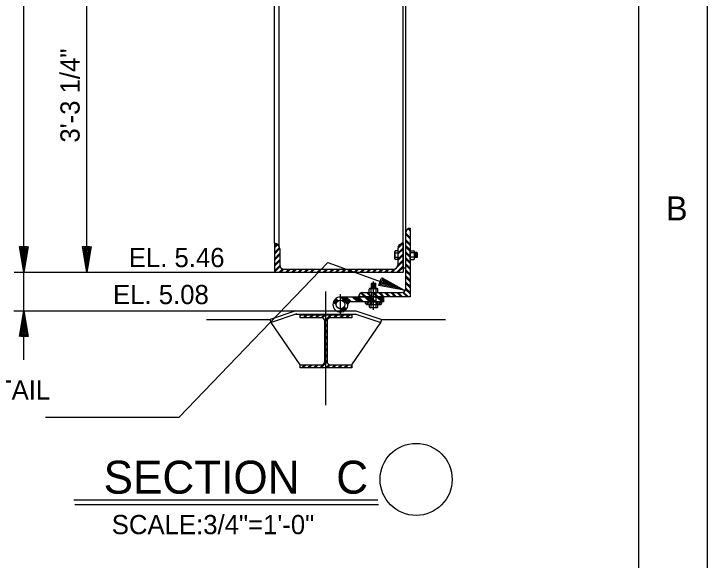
# Model space of a CAD drawing. Extents: x 0.6 to 54, y 0.6 to 38.
# Drawn here: x 47.23 to 53.96, y 11.41 to 16.72 of the extents above; entities that cross this region are included whole.
import ezdxf

# ---------------------------------------------------------------- set-up
doc = ezdxf.new("R2010")
doc.units = 0
for name, color, linetype in [('Level 1', 7, 'Continuous'), ('Level 10', 7, 'Continuous'), ('Level 13', 7, 'Continuous'), ('Level 2', 7, 'Continuous'), ('Level 25', 7, 'Continuous'), ('Level 3', 7, 'Continuous'), ('Level 36', 7, 'Continuous'), ('Level 50', 7, 'Continuous')]:
    doc.layers.add(name, color=color, linetype=linetype)

msp = doc.modelspace()

# ---------------------------------------------------------------- linework, layer by layer
at = {"layer": 'Level 1'}
msp.add_line((50.6601, 13.8913), (50.7804, 13.8913), dxfattribs=at)
for points in [[(0.625, 37.9583), (53.9583, 37.9583), (53.9583, 0.625), (0.625, 0.625)], [(2.625, 37.2917), (53.2917, 37.2917), (53.2917, 1.2917), (2.625, 1.2917)]]:
    msp.add_lwpolyline(points, close=True, dxfattribs=at)
for centre, start, end in [((50.6625, 13.9174), 180, 270), ((50.7771, 13.9174), 270, 0)]:
    msp.add_arc(centre, 0.026, start, end, dxfattribs=at)
at = {"layer": 'Level 10'}
for p, q in [((50.6431, 13.9174), (50.6372, 13.9115)), ((50.649, 13.9174), (50.6386, 13.907)), ((50.6725, 13.9174), (50.6498, 13.8947)), ((50.6784, 13.9174), (50.6539, 13.8928)), ((50.6956, 13.9109), (50.6759, 13.8913)), ((50.6956, 13.9051), (50.6818, 13.8913)), ((50.7684, 13.9174), (50.7441, 13.8931)), ((50.7625, 13.9174), (50.7441, 13.899)), ((50.7919, 13.9174), (50.7659, 13.8913)), ((50.7978, 13.9174), (50.7718, 13.8913))]:
    msp.add_line(p, q, dxfattribs=at)
at = {"layer": 'Level 13'}
for p, q in [((50.9252, 14.4087), (50.9284, 14.4143)), ((50.9252, 14.3362), (50.9252, 14.4087)), ((50.9591, 14.4143), (50.9284, 14.4143)), ((50.9591, 14.3306), (50.9591, 14.4143)), ((51.0743, 14.3306), (51.0743, 14.4143)), ((51.0743, 14.4143), (51.1141, 14.4143)), ((51.1173, 14.4087), (51.1141, 14.4143)), ((51.1173, 14.3362), (51.1173, 14.4087)), ((50.9283, 14.3934), (50.9591, 14.3934)), ((50.9283, 14.3515), (50.9591, 14.3515)), ((50.9606, 14.3967), (50.9591, 14.3967)), ((50.9591, 14.3518), (50.9591, 14.3306)), ((50.9606, 14.3482), (50.9591, 14.3482)), ((51.0728, 14.3967), (51.0743, 14.3967)), ((51.0728, 14.3482), (51.0743, 14.3482)), ((51.1142, 14.3934), (51.0743, 14.3934)), ((51.1142, 14.3515), (51.0743, 14.3515)), ((51.1408, 14.3967), (51.1173, 14.3967)), ((51.1408, 14.3482), (51.1173, 14.3482)), ((51.1226, 14.3544), (51.1226, 14.3904)), ((51.1286, 14.3482), (51.1286, 14.3967)), ((51.1347, 14.3544), (51.1347, 14.3904)), ((51.1408, 14.3482), (51.1408, 14.3967)), ((51.1408, 14.3967), (51.1468, 14.3907)), ((51.1408, 14.3482), (51.1468, 14.3543)), ((51.1468, 14.3543), (51.1468, 14.3907)), ((50.9252, 14.3362), (50.9284, 14.3306)), ((50.9591, 14.3306), (50.9284, 14.3306)), ((51.0743, 14.3306), (51.1141, 14.3306)), ((51.1173, 14.3362), (51.1141, 14.3306)), ((50.6993, 14.0974), (50.7015, 14.0996)), ((50.6993, 14.0975), (50.741, 14.0975)), ((50.6993, 14.0495), (50.6993, 14.0974)), ((50.6993, 14.0891), (50.741, 14.0891)), ((50.6993, 14.0809), (50.741, 14.0809)), ((50.6993, 14.0725), (50.741, 14.0725)), ((50.7015, 14.0996), (50.7389, 14.0996)), ((50.7098, 14.0934), (50.7316, 14.0934)), ((50.7098, 14.085), (50.7316, 14.085)), ((50.7098, 14.0766), (50.7316, 14.0766)), ((50.7098, 14.0684), (50.7316, 14.0684)), ((50.741, 14.0973), (50.7389, 14.0996)), ((50.741, 14.0495), (50.741, 14.0973)), ((50.6785, 14.0079), (50.6785, 14.0412)), ((50.687, 14.0495), (50.7534, 14.0495)), ((50.6957, 14.0079), (50.6957, 14.0412)), ((50.6993, 14.0641), (50.741, 14.0641)), ((50.6993, 14.0559), (50.741, 14.0559)), ((50.6993, 14.0079), (50.6993, 13.8906)), ((50.7098, 14.06), (50.7316, 14.06)), ((50.7098, 14.0516), (50.7316, 14.0516)), ((50.741, 14.0079), (50.741, 13.8906)), ((50.745, 14.0079), (50.745, 14.0412)), ((50.7618, 14.0079), (50.7618, 14.0412)), ((50.3383, 13.934), (50.361, 13.9113)), ((50.3398, 13.9362), (50.3623, 13.9137)), ((50.3414, 13.9383), (50.3634, 13.9162)), ((50.3431, 13.9403), (50.3653, 13.9181)), ((50.3448, 13.9422), (50.3669, 13.9201)), ((50.3466, 13.9441), (50.3687, 13.922)), ((50.3486, 13.9458), (50.3706, 13.9238)), ((50.3505, 13.9476), (50.3727, 13.9254)), ((50.3525, 13.9493), (50.3748, 13.927)), ((50.3545, 13.9509), (50.377, 13.9284)), ((50.8149, 13.9654), (50.3982, 13.9654)), ((50.3989, 13.9654), (50.4711, 13.8932)), ((50.4026, 13.9654), (50.4714, 13.8966)), ((50.4063, 13.9654), (50.4721, 13.8996)), ((50.4099, 13.9654), (50.4731, 13.9023)), ((50.4136, 13.9654), (50.4742, 13.9049)), ((50.4173, 13.9654), (50.4754, 13.9074)), ((50.421, 13.9654), (50.4772, 13.9093)), ((50.4247, 13.9654), (50.4791, 13.911)), ((50.4284, 13.9654), (50.4809, 13.9129)), ((50.4321, 13.9654), (50.4831, 13.9144)), ((50.4358, 13.9654), (50.4854, 13.9158)), ((50.4394, 13.9654), (50.488, 13.9169)), ((50.4431, 13.9654), (50.4908, 13.9178)), ((50.4468, 13.9654), (50.4939, 13.9184)), ((50.4505, 13.9654), (50.4974, 13.9186)), ((50.4541, 13.9654), (50.501, 13.9186)), ((50.4578, 13.9654), (50.5047, 13.9186)), ((50.5168, 13.9654), (50.5636, 13.9186)), ((50.5204, 13.9654), (50.5673, 13.9186)), ((50.5241, 13.9654), (50.571, 13.9186)), ((50.5278, 13.9654), (50.5747, 13.9186)), ((50.5315, 13.9654), (50.5784, 13.9186)), ((50.5315, 13.9654), (50.5747, 13.9223)), ((50.5352, 13.9654), (50.5821, 13.9186)), ((50.5389, 13.9654), (50.5857, 13.9186)), ((50.5426, 13.9654), (50.5894, 13.9186)), ((50.5462, 13.9654), (50.5931, 13.9186)), ((50.5499, 13.9654), (50.5968, 13.9186)), ((50.5536, 13.9654), (50.6005, 13.9186)), ((50.5573, 13.9654), (50.6042, 13.9186)), ((50.5609, 13.9654), (50.6078, 13.9186)), ((50.5646, 13.9654), (50.6115, 13.9186)), ((50.5683, 13.9654), (50.6152, 13.9186)), ((50.572, 13.9654), (50.6189, 13.9186)), ((50.5757, 13.9654), (50.6226, 13.9186)), ((50.6346, 13.9654), (50.6815, 13.9186)), ((50.6383, 13.9654), (50.6852, 13.9186)), ((50.642, 13.9654), (50.6889, 13.9186)), ((50.6457, 13.9654), (50.6926, 13.9186)), ((50.6493, 13.9654), (50.6962, 13.9186)), ((50.653, 13.9654), (50.6999, 13.9186)), ((50.6567, 13.9654), (50.7036, 13.9186)), ((50.6604, 13.9654), (50.7073, 13.9186)), ((50.6641, 13.9654), (50.7109, 13.9186)), ((50.6678, 13.9654), (50.7146, 13.9186)), ((50.6714, 13.9654), (50.7183, 13.9186)), ((50.6751, 13.9654), (50.722, 13.9186)), ((50.6788, 13.9654), (50.7257, 13.9186)), ((50.6825, 13.9654), (50.7294, 13.9186)), ((50.6862, 13.9654), (50.7331, 13.9186)), ((50.6899, 13.9654), (50.7367, 13.9186)), ((50.6935, 13.9654), (50.7404, 13.9186)), ((50.7524, 13.9654), (50.7993, 13.9186)), ((50.7561, 13.9654), (50.803, 13.9186)), ((50.7598, 13.9654), (50.8067, 13.9186)), ((50.7635, 13.9654), (50.8104, 13.9186)), ((50.7672, 13.9654), (50.8141, 13.9186)), ((50.7709, 13.9654), (50.8149, 13.9214)), ((50.7746, 13.9654), (50.8149, 13.9251)), ((50.7782, 13.9654), (50.8149, 13.9288)), ((50.7819, 13.9654), (50.8149, 13.9325)), ((50.7856, 13.9654), (50.8149, 13.9361)), ((50.7893, 13.9654), (50.8149, 13.9398)), ((50.7929, 13.9654), (50.8149, 13.9435)), ((50.7966, 13.9654), (50.8149, 13.9472)), ((50.8003, 13.9654), (50.8149, 13.9509)), ((50.804, 13.9654), (50.8149, 13.9546)), ((50.8077, 13.9654), (50.8149, 13.9583)), ((50.8114, 13.9654), (50.8149, 13.9619)), ((50.8149, 13.9654), (50.8149, 13.9186)), ((50.3295, 13.917), (50.3566, 13.8899)), ((50.3305, 13.9197), (50.3566, 13.8937)), ((50.3316, 13.9223), (50.3568, 13.8971)), ((50.3328, 13.9248), (50.3573, 13.9003)), ((50.3341, 13.9272), (50.358, 13.9033)), ((50.3354, 13.9295), (50.3588, 13.9061)), ((50.3368, 13.9318), (50.3598, 13.9088)), ((50.4311, 13.867), (50.4533, 13.8448)), ((50.4327, 13.8691), (50.4548, 13.847)), ((50.4341, 13.8713), (50.4566, 13.8488)), ((50.8149, 13.9186), (50.4972, 13.9186)), ((50.6791, 13.8913), (50.7624, 13.8913)), ((50.6791, 13.8678), (50.6791, 13.8913)), ((50.6963, 13.8676), (50.6963, 13.8913)), ((50.7456, 13.8677), (50.7456, 13.8913)), ((50.7624, 13.8678), (50.7624, 13.8913)), ((50.3956, 13.8509), (50.4227, 13.8238)), ((50.3993, 13.8509), (50.4254, 13.8248)), ((50.4028, 13.8511), (50.4279, 13.8259)), ((50.406, 13.8516), (50.4304, 13.8271)), ((50.409, 13.8523), (50.4329, 13.8284)), ((50.4118, 13.8531), (50.4352, 13.8297)), ((50.4145, 13.8542), (50.4375, 13.8311)), ((50.417, 13.8553), (50.4397, 13.8326)), ((50.4194, 13.8566), (50.4419, 13.8341)), ((50.4216, 13.8581), (50.4439, 13.8357)), ((50.4238, 13.8596), (50.4459, 13.8374)), ((50.4258, 13.8612), (50.4479, 13.8391)), ((50.4277, 13.8631), (50.4498, 13.8409)), ((50.4294, 13.8649), (50.4515, 13.8429)), ((50.6876, 13.8622), (50.7541, 13.8622))]:
    msp.add_line(p, q, dxfattribs=at)
msp.add_circle((50.3982, 13.8925), 0.0417, dxfattribs=at)
for centre, radius, start, end in [((50.9433, 14.4037), 0.0182, 149.71241, 214.51098), ((51.0992, 14.4038), 0.0182, 325.48902, 30.28759), ((50.9433, 14.3412), 0.0182, 145.48902, 210.28759), ((50.9979, 14.3722), 0.0727, 163.01837, 196.49659), ((51.0446, 14.3722), 0.0727, 343.50341, 16.98163), ((51.0992, 14.3412), 0.0182, 329.71241, 34.51098), ((50.6869, 14.041), 0.00844, 0.56585, 179.43412), ((50.7203, 14.009), 0.0406, 52.43432, 127.56565), ((50.7534, 14.0411), 0.00843, 0.4975, 179.50247), ((50.3982, 13.8925), 0.0729, 90, 0), ((50.4972, 13.8925), 0.026, 90, 180), ((50.6877, 13.8715), 0.00938, 203.16754, 335.99909), ((50.7208, 13.9191), 0.0569, 244.55188, 295.884), ((50.754, 13.8714), 0.00912, 202.37505, 337.19948)]:
    msp.add_arc(centre, radius, start, end, dxfattribs=at)
at = {"layer": 'Level 2'}
for p, q in [((50.6365, 13.9174), (50.8031, 13.9174)), ((50.6956, 13.8913), (50.6956, 13.9174)), ((50.7441, 13.8913), (50.7441, 13.9174))]:
    msp.add_line(p, q, dxfattribs=at)
at = {"layer": 'Level 25'}
for p, q in [((47.3239, 14.206), (47.3239, 20.7475)), ((49.7566, 14.4873), (49.7566, 19.2996)), ((49.8035, 14.4579), (49.8035, 19.2996)), ((51.0066, 14.2477), (51.0066, 19.2475)), ((51.0327, 14.2477), (51.0327, 19.2475)), ((47.9368, 14.206), (47.9368, 17.4766)), ((51.0743, 14.6086), (51.0548, 14.6281)), ((51.0743, 14.6246), (51.0667, 14.6322)), ((51.0743, 14.5441), (51.0327, 14.5857)), ((51.0743, 14.5304), (51.0327, 14.572)), ((49.7566, 14.4873), (49.7566, 14.206)), ((49.7815, 14.4809), (49.7566, 14.456)), ((49.7898, 14.4753), (49.7566, 14.4421)), ((51.0066, 14.5031), (50.957, 14.4535)), ((51.0066, 14.4892), (50.9571, 14.4396)), ((51.0066, 14.4873), (51.0066, 14.206)), ((51.0743, 14.4797), (51.0327, 14.5214)), ((51.0743, 14.4649), (51.0327, 14.5065)), ((49.8072, 14.4476), (49.7566, 14.3971)), ((49.8087, 14.4353), (49.7566, 14.3832)), ((49.8087, 14.4352), (49.8087, 14.2789)), ((50.9545, 14.4352), (50.9545, 14.2789)), ((51.0066, 14.4441), (50.9546, 14.3921)), ((51.0066, 14.4303), (50.9569, 14.3805)), ((51.0743, 14.4229), (51.0327, 14.4646)), ((51.0743, 14.409), (51.0327, 14.4507)), ((51.0743, 14.364), (51.0327, 14.4057)), ((49.8087, 14.3902), (49.7566, 14.3381)), ((49.8087, 14.3763), (49.7566, 14.3242)), ((51.0066, 14.3713), (50.9547, 14.3194)), ((51.0066, 14.3852), (50.955, 14.3336)), ((51.0743, 14.3501), (51.0327, 14.3918)), ((51.0743, 14.3051), (51.0327, 14.3467)), ((48.8338, 12.7979), (50.2758, 14.3016)), ((49.8087, 14.3304), (49.7566, 14.2783)), ((49.8087, 14.3165), (49.7566, 14.2645)), ((49.8087, 14.2715), (49.7566, 14.2194)), ((50.2758, 14.3016), (51.0179, 14.0309)), ((51.0066, 14.3124), (50.9002, 14.206)), ((51.0066, 14.3263), (50.9562, 14.2759)), ((51.0743, 14.2912), (51.0327, 14.3329)), ((51.0743, 14.2461), (51.0327, 14.2878)), ((51.0743, 14.2323), (51.0327, 14.2739)), ((47.2317, 14.206), (49.8992, 14.206)), ((47.3239, 13.8308), (47.3239, 14.206)), ((49.8126, 14.2614), (49.76, 14.2089)), ((49.8357, 14.2395), (49.8051, 14.2089)), ((49.8498, 14.2369), (49.8189, 14.206)), ((49.8984, 14.2355), (49.8683, 14.2054)), ((49.9142, 14.2375), (49.8822, 14.2054)), ((49.9569, 14.2351), (49.9272, 14.2054)), ((49.9716, 14.2359), (49.9411, 14.2054)), ((50.0168, 14.2361), (49.9862, 14.2054)), ((50.0309, 14.2363), (50.0001, 14.2054)), ((50.076, 14.2355), (50.046, 14.2054)), ((50.0919, 14.2375), (50.0598, 14.2054)), ((50.1345, 14.2379), (50.1049, 14.2083)), ((50.1493, 14.2388), (50.1188, 14.2083)), ((50.2031, 14.2366), (50.1731, 14.2066)), ((50.2189, 14.2386), (50.1869, 14.2066)), ((50.2616, 14.2362), (50.232, 14.2066)), ((50.2763, 14.237), (50.2459, 14.2066)), ((50.3216, 14.2372), (50.291, 14.2066)), ((50.3357, 14.2374), (50.3048, 14.2066)), ((50.3808, 14.2366), (50.3508, 14.2066)), ((50.3966, 14.2386), (50.3646, 14.2066)), ((50.4393, 14.2362), (50.4097, 14.2066)), ((50.454, 14.237), (50.4236, 14.2066)), ((50.4992, 14.2372), (50.4686, 14.2066)), ((50.5134, 14.2374), (50.4825, 14.2066)), ((50.5619, 14.2361), (50.5319, 14.206)), ((50.5778, 14.238), (50.5457, 14.206)), ((50.6204, 14.2356), (50.5908, 14.206)), ((50.6351, 14.2364), (50.6047, 14.206)), ((50.6804, 14.2366), (50.6498, 14.206)), ((50.6945, 14.2369), (50.6636, 14.206)), ((50.7396, 14.2361), (50.7096, 14.206)), ((50.7554, 14.238), (50.7234, 14.206)), ((50.7981, 14.2356), (50.7685, 14.206)), ((50.8128, 14.2364), (50.7824, 14.206)), ((50.8581, 14.2366), (50.8274, 14.206)), ((50.8722, 14.2369), (50.8413, 14.206)), ((50.9171, 14.2368), (50.8863, 14.206)), ((51.0066, 14.2674), (50.9453, 14.206)), ((51.0066, 14.2535), (50.9592, 14.206)), ((51.0066, 14.2084), (51.0042, 14.206)), ((51.0066, 14.2477), (51.0327, 14.2477)), ((51.0743, 14.1872), (51.0327, 14.2289)), ((51.0743, 14.1733), (51.0327, 14.215)), ((51.0743, 14.1283), (51.0327, 14.17)), ((51.0743, 14.1144), (51.0327, 14.1561)), ((50.7202, 13.8401), (50.7202, 14.1157)), ((51.0743, 14.0694), (51.0327, 14.111)), ((51.0743, 14.0555), (51.0327, 14.0971)), ((50.257, 12.9166), (50.257, 14.0188)), ((50.6333, 13.9662), (50.5966, 14.0028)), ((50.6471, 13.9662), (50.6068, 14.0066)), ((50.6922, 13.9662), (50.6505, 14.0079)), ((50.7061, 13.9662), (50.6644, 14.0079)), ((50.7511, 13.9662), (50.7094, 14.0079)), ((50.765, 13.9662), (50.7233, 14.0079)), ((50.81, 13.9662), (50.7684, 14.0079)), ((50.8239, 13.9662), (50.7823, 14.0079)), ((50.8689, 13.9662), (50.8273, 14.0079)), ((50.8828, 13.9662), (50.8412, 14.0079)), ((50.9279, 13.9662), (50.8862, 14.0079)), ((50.9418, 13.9662), (50.9001, 14.0079)), ((50.9868, 13.9662), (50.9451, 14.0079)), ((51.0007, 13.9662), (50.959, 14.0079)), ((51.0457, 13.9662), (51.0024, 14.0095)), ((51.0596, 13.9662), (51.012, 14.0138)), ((51.0743, 13.9966), (51.0311, 14.0398)), ((51.0743, 14.0104), (51.0327, 14.0521)), ((50.3972, 13.7906), (50.3972, 13.9926)), ((50.5882, 13.9662), (50.5762, 13.9783)), ((47.2277, 13.8308), (49.9654, 13.8308)), ((47.3239, 13.3551), (47.3239, 13.8308)), ((49.9654, 13.8308), (49.7154, 13.7475)), ((49.9752, 13.8012), (49.7252, 13.7178)), ((49.9654, 13.8308), (50.5487, 13.8308)), ((49.9654, 13.7996), (50.5487, 13.7996)), ((50.5388, 13.8012), (50.7888, 13.7178)), ((50.5487, 13.8308), (50.7987, 13.7475)), ((49.0965, 13.7475), (49.7154, 13.7475)), ((49.7253, 13.7178), (49.7154, 13.7475)), ((50.0065, 13.7939), (50.0065, 13.7939)), ((50.0065, 13.78), (50.0204, 13.7939)), ((50.035, 13.7635), (50.0654, 13.7939)), ((50.0489, 13.7635), (50.0793, 13.7939)), ((50.094, 13.7635), (50.1244, 13.7939)), ((50.1078, 13.7635), (50.1383, 13.7939)), ((50.1529, 13.7635), (50.1833, 13.7939)), ((50.1668, 13.7635), (50.1972, 13.7939)), ((50.2118, 13.7635), (50.2422, 13.7939)), ((50.2241, 13.7619), (50.2561, 13.7939)), ((50.2454, 13.7382), (50.3011, 13.7939)), ((50.2465, 13.7254), (50.315, 13.7939)), ((50.3297, 13.7635), (50.3601, 13.7939)), ((50.3435, 13.7635), (50.374, 13.7939)), ((50.3886, 13.7635), (50.419, 13.7939)), ((50.4025, 13.7635), (50.4329, 13.7939)), ((50.4475, 13.7635), (50.4779, 13.7939)), ((50.4614, 13.7635), (50.4918, 13.7939)), ((50.5064, 13.7635), (50.5082, 13.7653)), ((50.7888, 13.7178), (50.7987, 13.7475)), ((50.7987, 13.7475), (51.4182, 13.7475)), ((50.0065, 13.3077), (49.7252, 13.7178)), ((50.2465, 13.6804), (50.2682, 13.702)), ((50.2465, 13.6665), (50.2682, 13.6882)), ((50.5082, 13.3077), (50.7888, 13.7178)), ((50.2465, 13.6214), (50.2682, 13.6431)), ((50.2465, 13.6076), (50.2682, 13.6292)), ((50.2465, 13.5625), (50.2682, 13.5842)), ((50.2465, 13.5486), (50.2682, 13.5703)), ((50.2465, 13.5036), (50.2682, 13.5253)), ((50.2465, 13.4897), (50.2682, 13.5114)), ((50.2465, 13.4447), (50.2682, 13.4663)), ((50.2465, 13.4308), (50.2682, 13.4524)), ((50.2465, 13.3858), (50.2682, 13.4074)), ((50.197, 13.2773), (50.2682, 13.3485)), ((50.2109, 13.2773), (50.2689, 13.3353)), ((50.2465, 13.3719), (50.2682, 13.3935)), ((50.0202, 13.2773), (50.0506, 13.3077)), ((50.0341, 13.2773), (50.0645, 13.3077)), ((50.0791, 13.2773), (50.1095, 13.3077)), ((50.093, 13.2773), (50.1234, 13.3077)), ((50.138, 13.2773), (50.1684, 13.3077)), ((50.1519, 13.2773), (50.1823, 13.3077)), ((50.2559, 13.2773), (50.2888, 13.3102)), ((50.2698, 13.2773), (50.3002, 13.3077)), ((50.3148, 13.2773), (50.3452, 13.3077)), ((50.3287, 13.2773), (50.3591, 13.3077)), ((50.3737, 13.2773), (50.4042, 13.3077)), ((50.3876, 13.2773), (50.418, 13.3077)), ((50.4327, 13.2773), (50.4631, 13.3077)), ((50.4466, 13.2773), (50.477, 13.3077)), ((50.4916, 13.2773), (50.5082, 13.2939)), ((50.5055, 13.2773), (50.5082, 13.28)), ((47.5342, 12.7979), (48.8338, 12.7979)), ((47.8112, 11.9959), (50.7609, 11.9959)), ((47.8181, 11.949), (50.7678, 11.949))]:
    msp.add_line(p, q, dxfattribs=at)
at = {"layer": 'Level 3'}
msp.add_circle((51.1331, 12.1942), 0.35, dxfattribs=at)
at = {"layer": 'Level 36'}
for p, q in [((51.0743, 14.6329), (51.0743, 13.9662)), ((51.0327, 14.0496), (51.0327, 14.5915)), ((50.616, 14.0079), (50.991, 14.0079)), ((51.0743, 13.9662), (50.5743, 13.9662)), ((50.0065, 13.7939), (50.5082, 13.7939)), ((50.0065, 13.7635), (50.0065, 13.7939)), ((50.2144, 13.7635), (50.0065, 13.7635)), ((50.2465, 13.3398), (50.2465, 13.7314)), ((50.2682, 13.7314), (50.2682, 13.3398)), ((50.5082, 13.7635), (50.3003, 13.7635)), ((50.5082, 13.7939), (50.5082, 13.7635)), ((50.0065, 13.2773), (50.0065, 13.3077)), ((50.0065, 13.3077), (50.2144, 13.3077)), ((50.5082, 13.2773), (50.0065, 13.2773)), ((50.3003, 13.3077), (50.5082, 13.3077)), ((50.5082, 13.3077), (50.5082, 13.2773))]:
    msp.add_line(p, q, dxfattribs=at)
for centre, radius, start, end in [((51.0743, 14.5912), 0.0417, 90, 180), ((50.616, 13.9662), 0.0417, 90, 180), ((50.991, 14.0496), 0.0417, 270, 0), ((50.2144, 13.7314), 0.0321, 0, 90), ((50.3003, 13.7314), 0.0321, 90, 180), ((50.2144, 13.3398), 0.0321, 270, 0), ((50.3003, 13.3398), 0.0321, 180, 270)]:
    msp.add_arc(centre, radius, start, end, dxfattribs=at)
at = {"layer": 'Level 50'}
for p, q in [((47.3239, 14.2753), (47.3239, 14.2753)), ((47.9368, 14.2753), (47.9368, 14.2753)), ((47.3239, 14.206), (47.3239, 14.206)), ((47.9368, 14.206), (47.9368, 14.206)), ((49.7566, 14.206), (51.0066, 14.206)), ((49.8504, 14.2373), (50.9129, 14.2373)), ((50.9528, 14.0547), (50.9528, 14.0547)), ((51.0179, 14.0309), (51.0179, 14.0309)), ((47.3239, 13.8308), (47.3239, 13.8308)), ((47.3239, 13.7615), (47.3239, 13.7615))]:
    msp.add_line(p, q, dxfattribs=at)
for points in [[(47.3652, 14.4553), (47.3239, 14.206), (47.2825, 14.4553), (47.3532, 14.4553), (47.3239, 14.2753), (47.2959, 14.4447), (47.3412, 14.4447), (47.3239, 14.342), (47.3092, 14.434), (47.3279, 14.434), (47.3239, 14.4113)], [(47.9782, 14.4553), (47.9368, 14.206), (47.8955, 14.4553), (47.9662, 14.4553), (47.9368, 14.2753), (47.9088, 14.4447), (47.9542, 14.4447), (47.9368, 14.342), (47.9222, 14.434), (47.9408, 14.434), (47.9368, 14.4113)], [(50.7978, 14.1552), (51.0179, 14.0309), (50.7695, 14.0775), (50.7937, 14.1439), (50.9528, 14.0547), (50.7841, 14.0864), (50.7996, 14.129), (50.8901, 14.0775), (50.7987, 14.0953), (50.8051, 14.1128), (50.825, 14.1013)], [(47.2825, 13.5815), (47.3239, 13.8308), (47.3652, 13.5815), (47.2945, 13.5815), (47.3239, 13.7615), (47.3519, 13.5921), (47.3065, 13.5921), (47.3239, 13.6948), (47.3385, 13.6028), (47.3199, 13.6028), (47.3239, 13.6255)]]:
    msp.add_lwpolyline(points, dxfattribs=at)
for centre, radius, start, end in [((49.7566, 14.4352), 0.0521, 0, 90), ((51.0066, 14.4352), 0.0521, 90, 180), ((49.8504, 14.2789), 0.0417, 180, 270), ((50.9129, 14.2789), 0.0417, 270, 0)]:
    msp.add_arc(centre, radius, start, end, dxfattribs=at)

# ---------------------------------------------------------------- texts
at = {"layer": 'Level 1'}
msp.add_text('B', height=0.2337, dxfattribs=at).set_placement((53.5597, 14.7095))
at = {"layer": 'Level 2'}
msp.add_text('SECTION   C', height=0.32, dxfattribs=at).set_placement((48.0989, 12.0554))
at = {"layer": 'Level 25'}
msp.add_text('3\'-3 1/4"', height=0.18667, rotation=90, dxfattribs=at).set_placement((47.866, 15.4656))
for s, height, p in [('EL. 5.46', 0.18667, (48.3429, 14.2557)), ('EL. 5.08', 0.18667, (48.1904, 13.8965)), ('FOR SEAL DETAIL', 0.186667, (45.4028, 12.9691)), ('SCALE:3/4"=1\'-0"', 0.186667, (48.1779, 11.662))]:
    msp.add_text(s, height=height, dxfattribs=at).set_placement(p)

doc.saveas('drawing.dxf')
